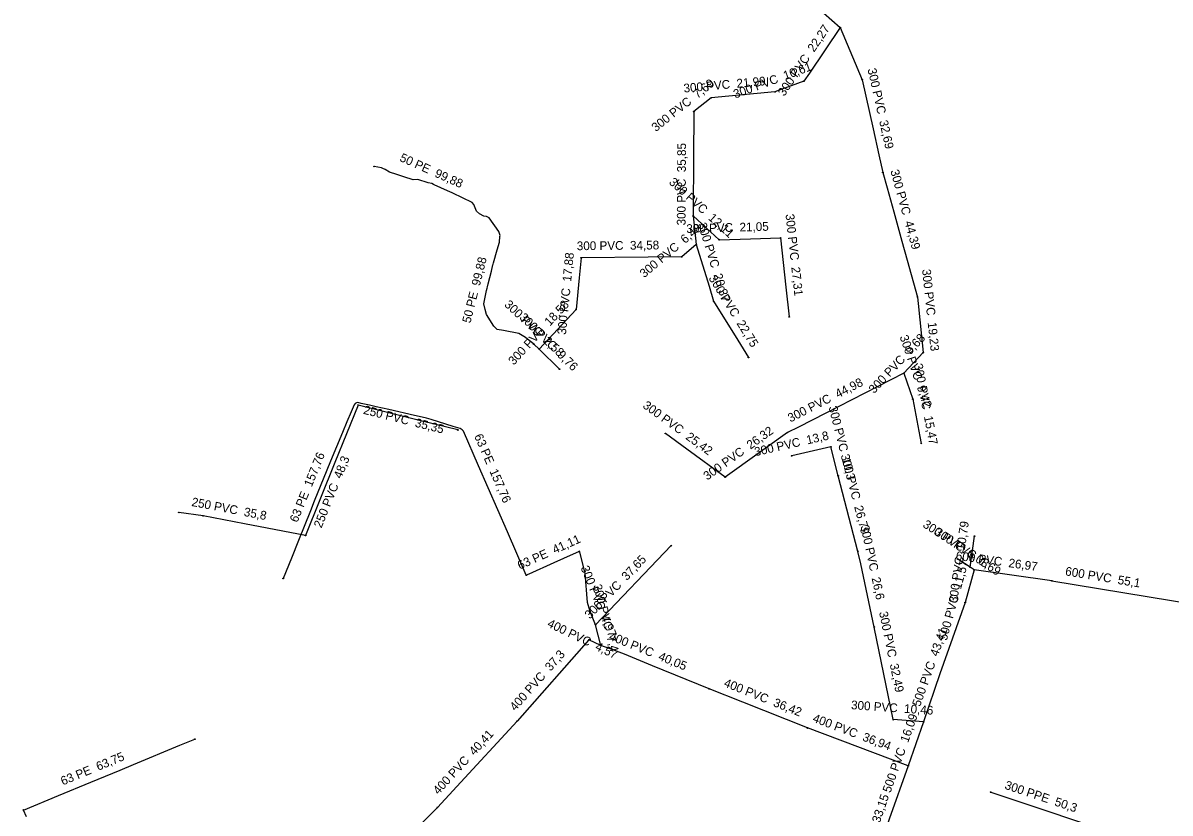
# Model space of a CAD drawing. Extents: x -736536 to -735428, y -1032997 to -1031649.
# Drawn here: x -736406 to -736011.6, y -1032358.4 to -1032086.9 of the extents above; entities that cross this region are included whole.
import ezdxf

# ---------------------------------------------------------------- set-up
doc = ezdxf.new("R2010")
doc.units = 0
for name, color, linetype in [('Vrstva 1', 7, 'Continuous'), ('Vrstva 20', 7, 'Continuous'), ('Vrstva 29', 7, 'Continuous'), ('Vrstva 63', 7, 'Continuous')]:
    doc.layers.add(name, color=color, linetype=linetype)

# ---------------------------------------------------------------- blocks, each defined once
blk = doc.blocks.new('100')
at = {"layer": 'Vrstva 1'}
blk.add_circle((0, 0), 0.127, dxfattribs=at)

msp = doc.modelspace()

# ---------------------------------------------------------------- linework, layer by layer
at = {"layer": 'Vrstva 20'}
for p, q in [((-736136.479, -1032078.281), (-736125.023, -1032088.502)), ((-736125.023, -1032088.502), (-736117.492, -1032106.42)), ((-736137.488, -1032106.953), (-736147.434, -1032110.636)), ((-736147.434, -1032110.636), (-736169.335, -1032112.621)), ((-736169.335, -1032112.621), (-736175.355, -1032117.405)), ((-736175.561, -1032153.251), (-736174.533, -1032163.102)), ((-736175.561, -1032153.251), (-736166.594, -1032161.395)), ((-736174.533, -1032163.102), (-736179.504, -1032167.259)), ((-736215.834, -1032185.392), (-736228.447, -1032199.03)), ((-736228.447, -1032199.03), (-736230.33, -1032197.266)), ((-736228.447, -1032199.03), (-736221.51, -1032205.901)), ((-736096.481, -1032200.216), (-736103.094, -1032207.285)), ((-736103.094, -1032207.285), (-736100.05, -1032216.196)), ((-736128.244, -1032232.58), (-736141.699, -1032235.642)), ((-736125.706, -1032242.566), (-736128.244, -1032232.58)), ((-736118.902, -1032268.48), (-736125.706, -1032242.566)), ((-736343.998, -1032256.309), (-736352.402, -1032255.097)), ((-736080.382, -1032273.952), (-736078.839, -1032263.275)), ((-736209.139, -1032293.696), (-736183.071, -1032266.526)), ((-736080.382, -1032273.952), (-736084.618, -1032271.15)), ((-736078.97, -1032274.886), (-736082.04, -1032286.04)), ((-736078.97, -1032274.886), (-736080.382, -1032273.952)), ((-736052.255, -1032278.592), (-736078.97, -1032274.886)), ((-736052.255, -1032278.592), (-735997.864, -1032287.553)), ((-736209.139, -1032293.696), (-736211.016, -1032289.094)), ((-736207.261, -1032300.856), (-736209.139, -1032293.696)), ((-736106.758, -1032326.31), (-736113.296, -1032294.484)), ((-736211.375, -1032298.873), (-736236.107, -1032326.796)), ((-736207.261, -1032300.856), (-736211.375, -1032298.873)), ((-736096.325, -1032327.031), (-736106.758, -1032326.31)), ((-736096.325, -1032327.031), (-736101.668, -1032342.212)), ((-736101.668, -1032342.212), (-736136.232, -1032329.174)), ((-736073.285, -1032351.22), (-736025.572, -1032367.158))]:
    msp.add_line(p, q, dxfattribs=at)
for points in [[(-736125.023, -1032088.502), (-736135.613, -1032104.177), (-736137.488, -1032106.953)], [(-736117.492, -1032106.42), (-736113.721, -1032123.252), (-736111.711, -1032132.22), (-736110.345, -1032138.319)], [(-736175.355, -1032117.405), (-736175.448, -1032133.516), (-736175.481, -1032139.4), (-736175.516, -1032145.426), (-736175.545, -1032150.425), (-736175.561, -1032153.251)], [(-736230.33, -1032197.266), (-736230.978, -1032196.728), (-736232.524, -1032195.53), (-736233.163, -1032195.035), (-736235.448, -1032193.575), (-736240.739, -1032192.617), (-736242.966, -1032192.218), (-736244.075, -1032191.054), (-736246.618, -1032187.086), (-736247.028, -1032185.365), (-736247.494, -1032183.399), (-736246.558, -1032178.862), (-736246.401, -1032178.1), (-736246.274, -1032177.593), (-736246.019, -1032176.578), (-736244.928, -1032172.234), (-736244.374, -1032170.028), (-736244.323, -1032169.823), (-736244.19, -1032169.354), (-736242.916, -1032164.867), (-736242.167, -1032162.23), (-736241.971, -1032160.314), (-736241.935, -1032159.962), (-736242.378, -1032158.586), (-736245.725, -1032153.931), (-736246.658, -1032153.426), (-736247.547, -1032153.275), (-736249.055, -1032152.524), (-736249.987, -1032151.576), (-736251.011, -1032149.306), (-736251.558, -1032148.644), (-736258.191, -1032145.371), (-736258.399, -1032145.297), (-736259.985, -1032144.589), (-736264.547, -1032142.552), (-736264.781, -1032142.429), (-736265.427, -1032142.088), (-736266.611, -1032141.825), (-736270.258, -1032140.68), (-736271.801, -1032140.813), (-736274.988, -1032139.833), (-736277.377, -1032139.038), (-736279.977, -1032138.172), (-736281.485, -1032137.301), (-736282.198, -1032136.982), (-736282.725, -1032136.745), (-736285.233, -1032136.207)], [(-736110.345, -1032138.319), (-736108.9, -1032143.538), (-736106.62, -1032151.771), (-736103.808, -1032161.925), (-736101.999, -1032168.46), (-736098.5, -1032181.096)], [(-736166.594, -1032161.395), (-736155.821, -1032161.087), (-736145.557, -1032160.794)], [(-736145.557, -1032160.794), (-736143.709, -1032177.687), (-736142.587, -1032187.945)], [(-736174.533, -1032163.102), (-736170.111, -1032177.424), (-736168.524, -1032182.562)], [(-736214.079, -1032167.602), (-736214.755, -1032174.459), (-736215.834, -1032185.392)], [(-736179.504, -1032167.259), (-736191.036, -1032167.373), (-736214.079, -1032167.602)], [(-736098.5, -1032181.096), (-736098.264, -1032183.327), (-736096.481, -1032200.216)], [(-736168.524, -1032182.562), (-736160.252, -1032195.893), (-736156.531, -1032201.89)], [(-736103.094, -1032207.285), (-736129.988, -1032220.971), (-736139.403, -1032225.762), (-736143.18, -1032227.684)], [(-736232.916, -1032276.644), (-736239.382, -1032261.815), (-736249.301, -1032239.068), (-736254.469, -1032227.216), (-736255.003, -1032226.747), (-736255.711, -1032226.29), (-736258.061, -1032225.557), (-736265.657, -1032223.188), (-736267.239, -1032222.695), (-736268.724, -1032222.361), (-736271.324, -1032221.777), (-736280.13, -1032219.798), (-736284.507, -1032218.815), (-736286.839, -1032218.272), (-736289.684, -1032217.639), (-736290.866, -1032217.379), (-736291.333, -1032217.432), (-736291.72, -1032217.654), (-736292.051, -1032218.141), (-736293.163, -1032220.554), (-736294.59, -1032223.938), (-736296.114, -1032227.625), (-736300.19, -1032237.484), (-736301.49, -1032240.631), (-736305.794, -1032251.28), (-736307.105, -1032254.536), (-736311.208, -1032264.742), (-736313.639, -1032270.862), (-736316.527, -1032277.802)], [(-736100.05, -1032216.196), (-736097.593, -1032229.008), (-736097.137, -1032231.387)], [(-736290.771, -1032218.216), (-736298.716, -1032237.924), (-736308.83, -1032263.013)], [(-736256.479, -1032226.784), (-736268.756, -1032223.717), (-736279.717, -1032220.978), (-736290.771, -1032218.216)], [(-736164.582, -1032242.999), (-736177.791, -1032233.354), (-736185.113, -1032228.007)], [(-736143.18, -1032227.684), (-736162.124, -1032241.24), (-736164.582, -1032242.999)], [(-736308.83, -1032263.013), (-736329.831, -1032259.01), (-736343.998, -1032256.309)], [(-736211.016, -1032289.094), (-736211.891, -1032286.096), (-736212.688, -1032276), (-736214.496, -1032268.81), (-736214.642, -1032268.429), (-736214.965, -1032268.599), (-736216.808, -1032269.429), (-736223.489, -1032272.44), (-736232.014, -1032276.28), (-736232.916, -1032276.644)], [(-736113.296, -1032294.484), (-736117.956, -1032272.727), (-736118.902, -1032268.48)], [(-736082.04, -1032286.04), (-736090.758, -1032310.62), (-736096.325, -1032327.031)], [(-736170.066, -1032315.7), (-736189.529, -1032307.772), (-736199.17, -1032303.844), (-736202.878, -1032302.41), (-736207.261, -1032300.856)], [(-736136.232, -1032329.174), (-736158.519, -1032320.298), (-736170.066, -1032315.7)], [(-736236.107, -1032326.796), (-736256.82, -1032349.25), (-736263.506, -1032356.498)], [(-736405.797, -1032357.367), (-736393.69, -1032352.362), (-736382.573, -1032347.766), (-736372.585, -1032343.637), (-736367.91, -1032341.704), (-736352.014, -1032335.133), (-736346.887, -1032333.005)], [(-736101.668, -1032342.212), (-736108.127, -1032360.465), (-736112.59, -1032373.51)], [(-736404.728, -1032359.652), (-736405.797, -1032357.367)], [(-736263.506, -1032356.498), (-736265.638, -1032358.63), (-736281.137, -1032373.894), (-736290.223, -1032382.841), (-736296.798, -1032389.317)]]:
    msp.add_lwpolyline(points, dxfattribs=at)

# ---------------------------------------------------------------- block references
at = {"layer": 'Vrstva 29'}
for p, xscale, yscale, rotation in [((-736125.023, -1032088.502), 1.000191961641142, 1.000191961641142, 97.08900113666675), ((-736137.488, -1032106.953), 0.9999999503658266, 0.9999999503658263, 37.999999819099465), ((-736117.492, -1032106.42), 0.9999999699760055, 0.9999999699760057, -73.00000033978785), ((-736147.434, -1032110.636), 1.0028916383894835, 1.0028916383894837, 13.697207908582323), ((-736169.335, -1032112.621), 1.025136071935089, 1.0251360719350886, 25.250758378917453), ((-736175.355, -1032117.405), 0.9999999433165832, 0.999999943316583, 64.0000000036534), ((-736285.233, -1032136.207), 1.0045862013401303, 1.00458620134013, 166.82590933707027), ((-736110.345, -1032138.319), 0.9999999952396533, 0.9999999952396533, -77.00000056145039), ((-736175.561, -1032153.251), 0.9999999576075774, 0.9999999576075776, -66.99999911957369), ((-736166.594, -1032161.395), 1.0275072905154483, 1.027507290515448, -24.689105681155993), ((-736145.557, -1032160.794), 0.9999999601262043, 0.9999999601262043, -41.999998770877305), ((-736174.533, -1032163.102), 0.9999999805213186, 0.9999999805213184, -79.00000058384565), ((-736214.079, -1032167.602), 0.9999999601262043, 0.9999999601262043, 41.999998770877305), ((-736179.504, -1032167.259), 1.0296949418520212, 1.0296949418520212, 24.133789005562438), ((-736098.5, -1032181.096), 0.9999999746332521, 0.9999999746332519, -80.00000055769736), ((-736215.834, -1032185.392), 0.9999999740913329, 0.9999999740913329, 65.99999939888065), ((-736168.524, -1032182.562), 0.9999999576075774, 0.9999999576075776, -66.99999911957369), ((-736142.587, -1032187.945), 0.9999999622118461, 0.999999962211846, -85.0000001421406), ((-736230.33, -1032197.266), 0.9999999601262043, 0.9999999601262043, -41.999998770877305), ((-736228.447, -1032199.03), 0.9999999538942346, 0.9999999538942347, 2.0000000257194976), ((-736096.481, -1032200.216), 0.9999999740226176, 0.9999999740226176, 71.00000039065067), ((-736156.531, -1032201.89), 0.9999999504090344, 0.9999999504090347, -58.99999841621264), ((-736221.51, -1032205.901), 0.9999999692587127, 0.9999999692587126, -46.00000080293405), ((-736103.094, -1032207.285), 0.9999999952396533, 0.9999999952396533, -102.9999994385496), ((-736100.05, -1032216.196), 0.9999999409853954, 0.9999999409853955, -75.99999967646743), ((-736290.771, -1032218.216), 1.0106517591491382, 1.010651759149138, 28.162115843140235), ((-736256.479, -1032226.784), 0.999999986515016, 0.9999999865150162, -15.000000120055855), ((-736185.113, -1032228.007), 0.9999999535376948, 0.9999999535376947, 143.99999865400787), ((-736143.18, -1032227.684), 0.9999999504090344, 0.9999999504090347, 31.000001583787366), ((-736128.244, -1032232.58), 0.9999999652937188, 0.9999999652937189, -31.9999973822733), ((-736097.137, -1032231.387), 0.9999999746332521, 0.9999999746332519, -80.00000055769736), ((-736141.699, -1032235.642), 1.0045862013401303, 1.00458620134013, -166.82590933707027), ((-736164.582, -1032242.999), 0.9999999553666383, 0.9999999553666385, -1.000000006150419), ((-736125.706, -1032242.566), 0.9999999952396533, 0.9999999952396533, -77.00000056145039), ((-736352.402, -1032255.097), 1.0092050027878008, 1.0092050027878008, 168.88308178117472), ((-736343.998, -1032256.309), 1.00837761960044, 1.00837761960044, 168.3736213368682), ((-736308.83, -1032263.013), 1.0037041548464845, 1.0037041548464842, 29.379208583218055), ((-736078.839, -1032263.275), 0.9999999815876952, 0.9999999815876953, 82.0000004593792), ((-736183.071, -1032266.526), 0.9999999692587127, 0.9999999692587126, 46.00000080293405), ((-736118.902, -1032268.48), 0.9999999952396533, 0.9999999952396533, -77.00000056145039), ((-736084.618, -1032271.15), 0.9999999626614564, 0.9999999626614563, 147.0000015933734), ((-736232.916, -1032276.644), 1.0296949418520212, 1.0296949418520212, 155.86621099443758), ((-736080.382, -1032273.952), 0.9999999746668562, 0.999999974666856, -34.00000045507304), ((-736078.97, -1032274.886), 1.025136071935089, 1.0251360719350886, -25.250758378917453), ((-736316.527, -1032277.802), 0.9999999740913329, 0.9999999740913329, -114.00000060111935), ((-736052.255, -1032278.592), 1.0073309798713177, 1.007330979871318, -12.138907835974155), ((-736082.04, -1032286.04), 0.9999999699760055, 0.9999999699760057, 73.00000033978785), ((-736211.016, -1032289.094), 0.9999999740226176, 0.9999999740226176, 108.99999960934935), ((-736209.139, -1032293.696), 1.0045862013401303, 1.00458620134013, -13.17409066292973), ((-736113.296, -1032294.484), 0.9999999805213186, 0.9999999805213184, -79.00000058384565), ((-736211.375, -1032298.873), 1.0060666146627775, 1.0060666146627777, 12.654735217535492), ((-736207.261, -1032300.856), 1.0198568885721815, 1.0198568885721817, -26.39398240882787), ((-736170.066, -1032315.7), 1.022584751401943, 1.022584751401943, -25.818974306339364), ((-736236.107, -1032326.796), 0.9999999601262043, 0.9999999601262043, 48.0000012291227), ((-736106.758, -1032326.31), 0.9999999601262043, 0.9999999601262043, -41.999998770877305), ((-736096.325, -1032327.031), 0.9999999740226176, 0.9999999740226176, 71.00000039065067), ((-736136.232, -1032329.174), 1.025136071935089, 1.0251360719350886, -25.250758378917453), ((-736346.887, -1032333.005), 1.022584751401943, 1.022584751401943, 25.818974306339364), ((-736101.668, -1032342.212), 0.9999999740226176, 0.9999999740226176, 71.00000039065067), ((-736073.285, -1032351.22), 1.0316957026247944, 1.0316957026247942, -23.584588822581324), ((-736405.797, -1032357.367), 0.999999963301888, 0.9999999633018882, 69.00000101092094), ((-736263.506, -1032356.498), 0.9999999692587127, 0.9999999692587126, 46.00000080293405)]:
    msp.add_blockref('100', p, dxfattribs=dict(at, xscale=xscale, yscale=yscale, rotation=rotation))

# ---------------------------------------------------------------- texts
at = {"layer": 'Vrstva 63'}
for s, rotation, p in [('300 PVC  22,27', 55.96, (-736144.247, -1032112.315)), ('300 PVC  10,61', 20.32, (-736161.092, -1032112.921)), ('300 PVC  32,69', 282.63, (-736115.634, -1032102.82)), ('300 PVC  7,69', 38.47, (-736188.39, -1032124.442)), ('300 PVC  21,99', 5.18, (-736178.735, -1032110.862)), ('300 PVC  35,85', 89.67, (-736178.179, -1032156.51)), ('50 PE  99,88', 335.94, (-736276.707, -1032134.274)), ('300 PVC  44,39', 285.48, (-736107.81, -1032137.732)), ('300 PVC  12,11', 317.75, (-736184.131, -1032141.953)), ('300 PVC  27,31', 276.24, (-736143.826, -1032152.688)), ('300 PVC  6,48', 39.9, (-736192.391, -1032174.645)), ('300 PVC  21,05', 1.64, (-736177.862, -1032159.117)), ('300 PVC  20,37', 287.16, (-736173.993, -1032156.035)), ('300 PVC  34,58', 0.57, (-736215.554, -1032165.017)), ('300 PVC  17,88', 84.37, (-736219.307, -1032194.134)), ('50 PE  99,88', 75.91, (-736252.132, -1032190.257)), ('300 PVC  22,75', 301.82, (-736170.384, -1032174.633)), ('300 PVC  19,23', 276.03, (-736096.882, -1032171.657)), ('300 PVC  2,58', 316.87, (-736240.69, -1032183.997)), ('300 PVC  18,58', 47.24, (-736237.232, -1032204.702)), ('300 PVC  9,76', 315.27, (-736235.506, -1032188.376)), ('300 PVC  9,68', 46.91, (-736113.366, -1032214.459)), ('300 PVC  9,42', 288.86, (-736104.631, -1032194.742)), ('300 PVC  15,47', 280.86, (-736099.696, -1032204.24)), ('300 PVC  44,98', 26.97, (-736142.106, -1032224.22)), ('300 PVC  25,42', 323.86, (-736193.14, -1032218.924)), ('250 PVC  35,35', 345.97, (-736289.15, -1032221.184)), ('300 PVC  10,3', 284.26, (-736129.031, -1032218.924)), ('63 PE  157,76', 293.56, (-736250.911, -1032228.868)), ('300 PVC  26,32', 35.59, (-736170.723, -1032244.197)), ('300 PVC  13,8', 12.82, (-736154.142, -1032235.807)), ('63 PE  157,76', 67.99, (-736311.626, -1032258.77)), ('250 PVC  48,3', 68.04, (-736303.358, -1032260.688)), ('300 PVC  26,79', 284.71, (-736124.879, -1032235.472)), ('250 PVC  35,8', 349.21, (-736348.16, -1032252.869)), ('300 PVC  26,6', 282.09, (-736118.062, -1032259.819)), ('300 PVC  5,08', 326.52, (-736096.879, -1032259.923)), ('300 PVC  1,69', 326.52, (-736092.815, -1032262.612)), ('300 PVC  10,79', 81.78, (-736084.802, -1032286.368)), ('63 PE  41,11', 24.25, (-736235.13, -1032274.831)), ('600 PVC  26,97', 352.1, (-736085.425, -1032271.364)), ('300 PVC  37,65', 46.19, (-736211.042, -1032291.926)), ('500 PVC  11,57', 74.61, (-736088.391, -1032299.318)), ('300 PVC  4,97', 292.19, (-736214.312, -1032274.128)), ('600 PVC  55,1', 350.64, (-736047.821, -1032276.685)), ('300 PVC  7,4', 284.7, (-736209.989, -1032280.207)), ('400 PVC  4,57', 334.27, (-736225.961, -1032294.248)), ('300 PVC  32,49', 281.61, (-736111.682, -1032289.418)), ('500 PVC  43,41', 70.47, (-736097.566, -1032322.038)), ('400 PVC  40,05', 337.84, (-736204.713, -1032298.78)), ('400 PVC  37,3', 48.47, (-736236.706, -1032323.552)), ('400 PVC  36,42', 338.29, (-736165.273, -1032314.811)), ('300 PVC  10,46', 356.05, (-736121.37, -1032322.695)), ('400 PVC  36,94', 339.33, (-736134.722, -1032326.963)), ('500 PVC  16,09', 70.61, (-736107.748, -1032351.655)), ('400 PVC  40,41', 47.31, (-736263.142, -1032352.269)), ('63 PE  63,75', 22.46, (-736392.234, -1032348.946)), ('300 PPE  50,3', 341.53, (-736068.694, -1032350.012)), ('500 PVC  33,15', 71.11, (-736117.329, -1032379.328))]:
    msp.add_text(s, height=2.99999, rotation=rotation, dxfattribs=at).set_placement(p)

doc.saveas('drawing.dxf')
